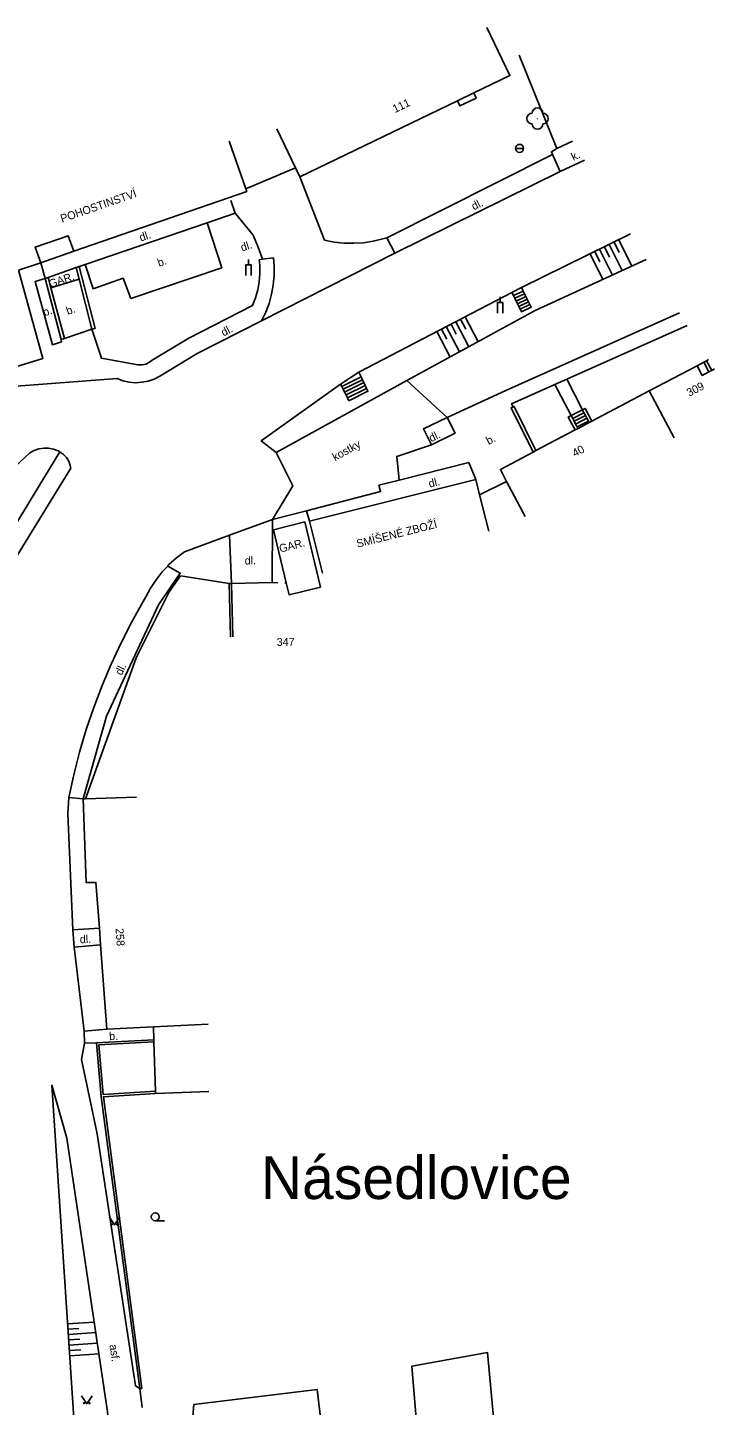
# Model space of a CAD drawing. Extents: x -582162 to -561283, y -1187583 to -1183539.
# Drawn here: x -574968.4 to -574904, y -1183847.8 to -1183718.7 of the extents above; entities that cross this region are included whole.
import ezdxf

# ---------------------------------------------------------------- set-up
doc = ezdxf.new("R2010")
doc.units = 0
for name, color, linetype in [('Vrstva 1', 7, 'Continuous'), ('Vrstva 10', 7, 'Continuous'), ('Vrstva 11', 7, 'Continuous'), ('Vrstva 12', 7, 'Continuous'), ('Vrstva 14', 7, 'Continuous'), ('Vrstva 17', 7, 'Continuous'), ('Vrstva 3', 7, 'Continuous'), ('Vrstva 4', 7, 'Continuous'), ('Vrstva 5', 7, 'Continuous'), ('Vrstva 6', 7, 'Continuous'), ('Vrstva 9', 7, 'Continuous')]:
    doc.layers.add(name, color=color, linetype=linetype)

# ---------------------------------------------------------------- blocks, each defined once
blk = doc.blocks.new('3.130')
at = {"layer": 'Vrstva 1'}
blk.add_circle((0, 0), 0.001, dxfattribs=at)
for centre, start, end in [((-1, 0), 90, 270), ((0, 1), 0, 180), ((1, 0), 270, 90), ((0, -1), 180, 360)]:
    blk.add_arc(centre, 1, start, end, dxfattribs=at)
blk = doc.blocks.new('3.040')
at = {"layer": 'Vrstva 1'}
blk.add_line((0, -0.75), (1.75, -0.75), dxfattribs=at)
blk.add_circle((0, 0), 0.75, dxfattribs=at)
blk = doc.blocks.new('3.140')
at = {"layer": 'Vrstva 1'}
blk.add_lwpolyline([(-1, 1.5), (0, 0), (1, 1.5)], dxfattribs=at)
for centre in [(-0.5, 0.1), (0.5, 0.1)]:
    blk.add_circle(centre, 0.1, dxfattribs=at)
blk = doc.blocks.new('4.120')
at = {"layer": 'Vrstva 1'}
blk.add_line((0, 2), (0, 3), dxfattribs=at)
blk.add_lwpolyline([(-0.5, 0), (-0.5, 2), (0.5, 2), (0.5, 0)], dxfattribs=at)
blk = doc.blocks.new('8.110')
at = {"layer": 'Vrstva 1'}
blk.add_line((-0.75, 0), (0.75, 0), dxfattribs=at)
blk.add_circle((0, 0), 0.75, dxfattribs=at)

msp = doc.modelspace()

# ---------------------------------------------------------------- linework, layer by layer
at = {"layer": 'Vrstva 10'}
for points in [[(-574918.8, -1183730.05), (-574922.35, -1183721.31)], [(-574919.2, -1183730.62), (-574919.32, -1183730.35), (-574918.8, -1183730.05)], [(-574918.8, -1183730.05), (-574917.33, -1183729.37)], [(-574934.73, -1183738.4), (-574919.2, -1183730.62)], [(-574919.2, -1183730.62), (-574918.49, -1183732.21)], [(-574918.49, -1183732.21), (-574916.22, -1183731.14)], [(-574942.91, -1183732.69), (-574940.59, -1183738.63), (-574939.69, -1183738.81), (-574938.77, -1183738.91), (-574937.85, -1183738.93), (-574936.92, -1183738.87), (-574936.01, -1183738.74), (-574935.12, -1183738.52), (-574934.73, -1183738.4)], [(-574934, -1183739.85), (-574918.49, -1183732.21)], [(-574949.38, -1183734.93), (-574948.96, -1183736.11)], [(-574951.6, -1183737), (-574948.96, -1183736.11)], [(-574948.96, -1183736.11), (-574947.29, -1183738.15), (-574946.82, -1183739.28), (-574946.41, -1183740.43)], [(-574963.02, -1183740.91), (-574951.6, -1183737)], [(-574934.73, -1183738.4), (-574934, -1183739.85)], [(-574911.91, -1183738.05), (-574922.12, -1183743.08)], [(-574946.41, -1183740.43), (-574946.71, -1183740.47), (-574946.66, -1183740.97), (-574946.64, -1183741.75), (-574946.7, -1183742.53), (-574946.84, -1183743.3), (-574947.06, -1183744.05), (-574947.35, -1183744.77), (-574953.31, -1183747.82), (-574956.73, -1183749.88), (-574956.99, -1183750.08), (-574957.33, -1183750.24), (-574957.7, -1183750.32), (-574958.08, -1183750.33), (-574961.5, -1183749.7), (-574962.39, -1183746.99)], [(-574946.48, -1183746.19), (-574934, -1183739.85)], [(-574946.48, -1183746.19), (-574946.1, -1183745.39), (-574945.78, -1183744.56), (-574945.55, -1183743.71), (-574945.39, -1183742.84), (-574945.31, -1183741.96), (-574945.31, -1183741.07), (-574945.38, -1183740.28), (-574946.41, -1183740.43)], [(-574932.86, -1183751.8), (-574920.83, -1183745.22), (-574910.42, -1183740.45)], [(-574969.26, -1183741.46), (-574966.98, -1183749.72), (-574970.34, -1183750.75)], [(-574966.79, -1183742.22), (-574967.19, -1183740.75)], [(-574963.87, -1183741.21), (-574966.5, -1183742.12)], [(-574963.58, -1183741.11), (-574963.87, -1183741.21)], [(-574963.02, -1183740.91), (-574963.58, -1183741.11)], [(-574962.29, -1183743.19), (-574963.02, -1183740.91)], [(-574965.26, -1183747.93), (-574965.23, -1183748.17), (-574966.1, -1183748.44), (-574967.72, -1183742.52), (-574966.79, -1183742.22)], [(-574966.5, -1183742.12), (-574966.79, -1183742.22)], [(-574923.01, -1183743.54), (-574937.36, -1183751)], [(-574929.1, -1183755.24), (-574923.6, -1183752.73), (-574907.31, -1183745.43)], [(-574946.48, -1183746.19), (-574952.52, -1183749.26), (-574956.03, -1183751.39), (-574956.56, -1183751.65), (-574957.12, -1183751.84), (-574957.71, -1183751.95), (-574958.3, -1183751.99), (-574958.9, -1183751.94), (-574959.48, -1183751.81), (-574960.04, -1183751.61), (-574969.88, -1183752.34)], [(-574906.58, -1183746.62), (-574917.88, -1183751.67)], [(-574962.39, -1183746.99), (-574964.97, -1183747.86)], [(-574945.12, -1183758.54), (-574946.51, -1183757.43), (-574939.08, -1183752.13)], [(-574945.12, -1183758.54), (-574932.86, -1183751.8)], [(-574929.1, -1183755.24), (-574932.86, -1183751.8)], [(-574917.88, -1183751.67), (-574918.98, -1183752.15)], [(-574917.88, -1183751.67), (-574916.41, -1183754.54)], [(-574918.98, -1183752.15), (-574923.04, -1183753.97), (-574922.9, -1183754.25)], [(-574917.47, -1183755.07), (-574918.98, -1183752.15)], [(-574930.54, -1183757.82), (-574931.32, -1183756.32), (-574929.1, -1183755.24)], [(-574930.54, -1183757.82), (-574928.34, -1183756.73), (-574929.1, -1183755.24)], [(-574965.4, -1183758.48), (-574965.57, -1183758.39), (-574966, -1183758.22), (-574966.45, -1183758.13), (-574966.91, -1183758.12), (-574967.36, -1183758.19), (-574967.8, -1183758.34), (-574968.2, -1183758.56), (-574984.34, -1183773.6)], [(-574973.93, -1183786.74), (-574974.04, -1183777.79), (-574970.76, -1183770.38), (-574964.37, -1183760), (-574964.42, -1183759.74), (-574964.57, -1183759.36), (-574964.79, -1183759.01), (-574965.07, -1183758.72), (-574965.4, -1183758.48)], [(-574965.4, -1183758.48), (-574972.13, -1183769.48), (-574973.68, -1183772.66)], [(-574945.12, -1183758.54), (-574943.56, -1183761.66), (-574945.47, -1183764.82)], [(-574933.58, -1183761.12), (-574933.81, -1183758.9), (-574930.54, -1183757.82)], [(-574933.58, -1183761.12), (-574927.06, -1183759.46), (-574926.4, -1183761.05)], [(-574942.29, -1183763.99), (-574935.33, -1183762.19), (-574935.49, -1183761.6), (-574933.58, -1183761.12)], [(-574945.47, -1183764.82), (-574949.5, -1183766.29)], [(-574945.47, -1183764.82), (-574945.49, -1183770.7)], [(-574942.29, -1183763.99), (-574945.47, -1183764.82)], [(-574941.99, -1183764.98), (-574942.29, -1183763.99)], [(-574949.5, -1183766.29), (-574953.71, -1183767.83), (-574954.47, -1183768.41), (-574955.17, -1183769.04), (-574955.29, -1183769.17)], [(-574949.5, -1183766.29), (-574949.32, -1183770.8)], [(-574955.29, -1183769.17), (-574955.81, -1183769.72), (-574956.38, -1183770.46), (-574956.9, -1183771.25), (-574957.34, -1183772.07), (-574957.59, -1183772.5), (-574958.66, -1183774.41), (-574959.66, -1183776.37), (-574960.59, -1183778.36), (-574961.44, -1183780.38), (-574962.22, -1183782.43), (-574962.92, -1183784.5), (-574963.55, -1183786.61), (-574964.1, -1183788.73), (-574964.57, -1183790.87)], [(-574955.29, -1183769.17), (-574954.11, -1183769.84), (-574956.14, -1183772.82), (-574961.03, -1183783.25), (-574963.2, -1183790.99)], [(-574964.57, -1183790.87), (-574964.64, -1183792.4), (-574964.19, -1183803.27)], [(-574963.2, -1183790.99), (-574964.57, -1183790.87)], [(-574964.19, -1183803.27), (-574961.69, -1183803.12)], [(-574964.19, -1183803.27), (-574964.06, -1183804.88)], [(-574964.06, -1183804.88), (-574961.58, -1183804.66)], [(-574964.06, -1183804.88), (-574963.12, -1183812.75)], [(-574963.12, -1183812.75), (-574961, -1183812.57)], [(-574963.12, -1183812.75), (-574963.08, -1183813.89)], [(-574963.08, -1183813.89), (-574963.38, -1183815.41), (-574961.9, -1183822.39), (-574958.31, -1183845.99), (-574957.91, -1183846.26)], [(-574963.08, -1183813.89), (-574961.95, -1183813.84)], [(-574962.62, -1183871.23), (-574966.14, -1183817.83), (-574964.73, -1183822.79), (-574960.94, -1183848.43), (-574960.22, -1183856.5)]]:
    msp.add_lwpolyline(points, dxfattribs=at)
at = {"layer": 'Vrstva 12'}
for points in [[(-574913.89, -1183739.03), (-574912.68, -1183741.49)], [(-574913.44, -1183738.81), (-574912.96, -1183739.8)], [(-574912.99, -1183738.59), (-574911.77, -1183741.07)], [(-574915.69, -1183739.92), (-574914.5, -1183742.32)], [(-574915.24, -1183739.69), (-574914.76, -1183740.66)], [(-574914.79, -1183739.47), (-574913.59, -1183741.91)], [(-574914.34, -1183739.25), (-574913.86, -1183740.23)], [(-574929.61, -1183746.97), (-574929.12, -1183747.92)], [(-574929.17, -1183746.74), (-574927.94, -1183749.11)], [(-574928.72, -1183746.51), (-574928.23, -1183747.45)], [(-574928.28, -1183746.28), (-574927.06, -1183748.63)], [(-574927.84, -1183746.05), (-574927.35, -1183746.98)], [(-574927.39, -1183745.82), (-574926.18, -1183748.15)], [(-574930.06, -1183747.2), (-574928.81, -1183749.59)], [(-574964.67, -1183840.18), (-574962.19, -1183840.02)], [(-574964.64, -1183840.68), (-574963.63, -1183840.62)], [(-574964.6, -1183841.18), (-574962.04, -1183841.01)], [(-574964.57, -1183841.68), (-574963.53, -1183841.61)], [(-574964.54, -1183842.18), (-574961.89, -1183842)], [(-574964.5, -1183842.68), (-574963.43, -1183842.61)], [(-574964.47, -1183843.18), (-574961.75, -1183843)]]:
    msp.add_lwpolyline(points, dxfattribs=at)
at = {"layer": 'Vrstva 4'}
for points in [[(-574926.59, -1183724.84), (-574923.2, -1183723.21), (-574925.37, -1183718.71)], [(-574928.13, -1183725.58), (-574926.59, -1183724.84)], [(-574942.91, -1183732.69), (-574928.13, -1183725.58)], [(-574945.07, -1183728.19), (-574943.32, -1183731.84)], [(-574949.51, -1183729.35), (-574947.96, -1183733.83)], [(-574943.32, -1183731.84), (-574942.91, -1183732.69)], [(-574947.96, -1183733.83), (-574947.88, -1183734.07), (-574964.1, -1183739.68)], [(-574964.1, -1183739.68), (-574964.61, -1183738.22), (-574967.7, -1183739.29), (-574967.19, -1183740.75)], [(-574964.1, -1183739.68), (-574967.19, -1183740.75)], [(-574967.19, -1183740.75), (-574969.26, -1183741.46)], [(-574910.14, -1183752.75), (-574905.66, -1183750.4)], [(-574905.66, -1183750.4), (-574905.18, -1183751.31), (-574904.55, -1183750.98)], [(-574904.55, -1183750.98), (-574904.28, -1183750.84)], [(-574904.28, -1183750.84), (-574904.03, -1183750.7)], [(-574915.51, -1183755.59), (-574910.14, -1183752.75)], [(-574907.8, -1183757.17), (-574910.14, -1183752.75)], [(-574916.81, -1183756.28), (-574915.78, -1183755.73)], [(-574915.78, -1183755.73), (-574915.51, -1183755.59)], [(-574920.76, -1183758.36), (-574917.08, -1183756.42)], [(-574917.08, -1183756.42), (-574916.81, -1183756.28)], [(-574923.51, -1183761.24), (-574924.1, -1183760.12), (-574921.02, -1183758.5)], [(-574921.02, -1183758.5), (-574920.76, -1183758.36)], [(-574941.99, -1183764.98), (-574926.4, -1183761.05)], [(-574926.4, -1183761.05), (-574926.04, -1183762.49)], [(-574921.77, -1183764.54), (-574923.51, -1183761.24)], [(-574926.04, -1183762.49), (-574925.18, -1183765.9)], [(-574942.44, -1183765.04), (-574945.38, -1183765.79), (-574944.18, -1183770.75)], [(-574944.18, -1183770.75), (-574943.91, -1183771.86), (-574940.96, -1183771.15), (-574942.44, -1183765.04)], [(-574940.77, -1183769.83), (-574941.99, -1183764.98)], [(-574963.2, -1183790.99), (-574962.99, -1183790.98), (-574958.21, -1183790.83)], [(-574961.69, -1183803.12), (-574962.01, -1183798.82), (-574962.94, -1183798.83), (-574963.2, -1183790.99)], [(-574961.58, -1183804.66), (-574961.69, -1183803.12)], [(-574961, -1183812.57), (-574961.58, -1183804.66)], [(-574956.63, -1183812.35), (-574961, -1183812.57)], [(-574951.5, -1183812.1), (-574956.63, -1183812.35)], [(-574956.63, -1183812.35), (-574956.59, -1183813.56)], [(-574956.59, -1183813.56), (-574956.58, -1183813.76)], [(-574956.58, -1183813.76), (-574956.43, -1183818.39)], [(-574956.43, -1183818.39), (-574956.42, -1183818.59)], [(-574956.42, -1183818.59), (-574951.42, -1183818.42)]]:
    msp.add_lwpolyline(points, dxfattribs=at)
at = {"layer": 'Vrstva 5'}
msp.add_lwpolyline([(-574953.37, -1183854.01), (-574952.83, -1183847.74), (-574941.28, -1183846.35), (-574940.53, -1183852.61), (-574946.79, -1183853.36), (-574947.56, -1183862.26), (-574938.66, -1183863.03), (-574938.82, -1183864.91), (-574930.62, -1183865.61), (-574932.39, -1183844.15), (-574925.3, -1183842.88), (-574923.17, -1183865.83), (-574921.49, -1183866.05), (-574921.56, -1183868.59)], dxfattribs=at)
at = {"layer": 'Vrstva 9'}
for points in [[(-574928.13, -1183725.58), (-574927.9, -1183726.06), (-574926.36, -1183725.32), (-574926.59, -1183724.84)], [(-574947.96, -1183733.83), (-574943.32, -1183731.84)], [(-574951.6, -1183737), (-574950.22, -1183741.22), (-574958.74, -1183744.1), (-574959.46, -1183742.21), (-574962.29, -1183743.19)], [(-574963.59, -1183742.3), (-574963.87, -1183741.21)], [(-574962.39, -1183746.99), (-574962.1, -1183746.91), (-574963.58, -1183741.11)], [(-574966.79, -1183742.22), (-574965.26, -1183747.93)], [(-574966.5, -1183742.12), (-574966.24, -1183743.1)], [(-574966.24, -1183743.1), (-574963.59, -1183742.3)], [(-574964.97, -1183747.86), (-574966.24, -1183743.1)], [(-574963.59, -1183742.3), (-574962.39, -1183746.99)], [(-574922.12, -1183743.08), (-574923.01, -1183743.54)], [(-574922.12, -1183743.08), (-574921.96, -1183743.4)], [(-574922.87, -1183743.83), (-574923.01, -1183743.54)], [(-574921.96, -1183743.4), (-574922.87, -1183743.83)], [(-574922.74, -1183744.08), (-574922.87, -1183743.83)], [(-574921.84, -1183743.65), (-574922.74, -1183744.08)], [(-574922.61, -1183744.34), (-574922.74, -1183744.08)], [(-574921.71, -1183743.91), (-574922.61, -1183744.34)], [(-574922.49, -1183744.59), (-574922.61, -1183744.34)], [(-574921.59, -1183744.16), (-574922.49, -1183744.59)], [(-574921.96, -1183743.4), (-574921.84, -1183743.65)], [(-574921.84, -1183743.65), (-574921.71, -1183743.91)], [(-574921.71, -1183743.91), (-574921.59, -1183744.16)], [(-574921.59, -1183744.16), (-574921.46, -1183744.41)], [(-574922.37, -1183744.84), (-574922.49, -1183744.59)], [(-574921.46, -1183744.41), (-574922.37, -1183744.84)], [(-574922.24, -1183745.09), (-574922.37, -1183744.84)], [(-574921.34, -1183744.66), (-574922.24, -1183745.09)], [(-574921.34, -1183744.66), (-574921.21, -1183744.91), (-574922.12, -1183745.34), (-574922.24, -1183745.09)], [(-574921.46, -1183744.41), (-574921.34, -1183744.66)], [(-574965.26, -1183747.93), (-574964.97, -1183747.86)], [(-574905.66, -1183750.4), (-574905.02, -1183750.07)], [(-574905.02, -1183750.07), (-574904.76, -1183749.93)], [(-574904.55, -1183750.98), (-574905.02, -1183750.07)], [(-574904.76, -1183749.93), (-574904.57, -1183749.83)], [(-574904.28, -1183750.84), (-574904.76, -1183749.93)], [(-574937.36, -1183751), (-574939.08, -1183752.13)], [(-574939.08, -1183752.13), (-574938.97, -1183752.34)], [(-574938.97, -1183752.34), (-574937.15, -1183751.44)], [(-574938.84, -1183752.6), (-574937.03, -1183751.71)], [(-574938.71, -1183752.87), (-574936.9, -1183751.98)], [(-574937.15, -1183751.44), (-574937.36, -1183751)], [(-574937.03, -1183751.71), (-574937.15, -1183751.44)], [(-574936.9, -1183751.98), (-574937.03, -1183751.71)], [(-574936.77, -1183752.25), (-574936.9, -1183751.98)], [(-574938.97, -1183752.34), (-574938.84, -1183752.6)], [(-574938.84, -1183752.6), (-574938.71, -1183752.87)], [(-574938.71, -1183752.87), (-574938.57, -1183753.14)], [(-574938.57, -1183753.14), (-574936.77, -1183752.25)], [(-574938.57, -1183753.14), (-574938.44, -1183753.41)], [(-574938.44, -1183753.41), (-574938.3, -1183753.68), (-574936.51, -1183752.79), (-574936.64, -1183752.52)], [(-574938.44, -1183753.41), (-574936.64, -1183752.52)], [(-574936.64, -1183752.52), (-574936.77, -1183752.25)], [(-574922.9, -1183754.25), (-574923.09, -1183754.34), (-574921.02, -1183758.5)], [(-574920.76, -1183758.36), (-574922.82, -1183754.21), (-574922.9, -1183754.25)], [(-574917.47, -1183755.07), (-574916.41, -1183754.54)], [(-574915.51, -1183755.59), (-574916.15, -1183754.4), (-574916.41, -1183754.54)], [(-574916.27, -1183754.8), (-574916.41, -1183754.54)], [(-574917.08, -1183756.42), (-574917.73, -1183755.22), (-574917.47, -1183755.07)], [(-574917.32, -1183755.34), (-574917.47, -1183755.07)], [(-574917.32, -1183755.34), (-574916.27, -1183754.8)], [(-574917.18, -1183755.6), (-574917.32, -1183755.34)], [(-574917.18, -1183755.6), (-574916.13, -1183755.07)], [(-574917.04, -1183755.87), (-574917.18, -1183755.6)], [(-574917.04, -1183755.87), (-574915.99, -1183755.33)], [(-574916.9, -1183756.13), (-574917.04, -1183755.87)], [(-574916.9, -1183756.13), (-574915.85, -1183755.6)], [(-574916.13, -1183755.07), (-574916.27, -1183754.8)], [(-574915.99, -1183755.33), (-574916.13, -1183755.07)], [(-574915.85, -1183755.6), (-574915.99, -1183755.33)], [(-574915.78, -1183755.73), (-574915.85, -1183755.6)], [(-574916.81, -1183756.28), (-574916.9, -1183756.13)], [(-574923.51, -1183761.24), (-574926.04, -1183762.49)], [(-574962.99, -1183790.98), (-574958.24, -1183777.77), (-574955.16, -1183771.59), (-574954.08, -1183770.1), (-574949.52, -1183770.8)], [(-574949.39, -1183775.8), (-574949.52, -1183770.8)], [(-574949.52, -1183770.8), (-574949.32, -1183770.8)], [(-574945.49, -1183770.7), (-574949.32, -1183770.8)], [(-574949.19, -1183775.8), (-574949.32, -1183770.8)], [(-574945.49, -1183770.7), (-574944.97, -1183770.75)], [(-574944.31, -1183770.75), (-574944.18, -1183770.75)], [(-574961.95, -1183813.84), (-574956.59, -1183813.56)], [(-574961.51, -1183818.92), (-574961.95, -1183813.84)], [(-574956.58, -1183813.76), (-574961.73, -1183814.03), (-574961.33, -1183818.71), (-574956.43, -1183818.39)], [(-574957.91, -1183846.26), (-574961.51, -1183818.92)], [(-574957.91, -1183846.26), (-574957.71, -1183846.24), (-574961.31, -1183818.91), (-574956.42, -1183818.59)], [(-574957.91, -1183846.26), (-574957.69, -1183848.02)]]:
    msp.add_lwpolyline(points, dxfattribs=at)

# ---------------------------------------------------------------- block references
at = {"layer": 'Vrstva 11', "xscale": 0.5, "yscale": 0.5}
msp.add_blockref('3.130', (-574920.62, -1183727.24), dxfattribs=at)
at = {"layer": 'Vrstva 3', "xscale": 0.5, "yscale": 0.5}
for name, p in [('3.140', (-574960.28, -1183830.92)), ('3.040', (-574956.46, -1183830.16)), ('3.140', (-574962.88, -1183847.67))]:
    msp.add_blockref(name, p, dxfattribs=at)
at = {"layer": 'Vrstva 9', "xscale": 0.5, "yscale": 0.5}
for name, p in [('8.110', (-574922.3, -1183730.03)), ('4.120', (-574947.7, -1183741.95)), ('4.120', (-574924.13, -1183745.46))]:
    msp.add_blockref(name, p, dxfattribs=at)

# ---------------------------------------------------------------- texts
at = {"layer": 'Vrstva 14'}
for s, rotation, p in [('k.', 26.214, (-574917.24, -1183731.21)), ('POHOSTINSTVÍ', 19.065, (-574965.19, -1183737)), ('dl.', 26.214, (-574926.58, -1183735.85)), ('dl.', 18.879, (-574957.8, -1183738.77)), ('dl.', 18.359, (-574948.31, -1183739.7)), ('b.', 18.879, (-574956.1, -1183741.14)), ('GAR.', 18.879, (-574966.28, -1183743.11)), ('b.', 18.879, (-574966.84, -1183745.78)), ('b.', 18.655, (-574964.66, -1183745.65)), ('dl.', 26.894, (-574950.05, -1183747.67)), ('dl.', 26.221, (-574930.58, -1183757.57)), ('b.', 27.845, (-574925.2, -1183757.83)), ('kostky', 28.818, (-574939.6, -1183759.35)), ('dl.', 14.139, (-574930.73, -1183761.83)), ('SMÍŠENÉ ZBOŽÍ', 14.139, (-574937.48, -1183767.46)), ('GAR.', 14.361, (-574944.73, -1183767.92)), ('dl.', 1.54, (-574948.06, -1183769.04)), ('dl.', 64.898, (-574959.59, -1183779.47)), ('dl.', 2.868, (-574963.51, -1183804.53)), ('b.', 2.868, (-574960.76, -1183813.61)), ('asf.', 278.393, (-574960.75, -1183842.17))]:
    msp.add_text(s, height=0.75, rotation=rotation, dxfattribs=at).set_placement(p)
at = {"layer": 'Vrstva 17'}
msp.add_text('Násedlovice', height=4, dxfattribs=at).set_placement((-574946.55, -1183828.49))
at = {"layer": 'Vrstva 6'}
for s, rotation, p in [('111', 25.694, (-574933.98, -1183726.73)), ('309', 27.65, (-574906.39, -1183753.32)), ('40', 27.845, (-574917.12, -1183758.98)), ('258', 274.192, (-574960.18, -1183803.14))]:
    msp.add_text(s, height=0.75, rotation=rotation, dxfattribs=at).set_placement(p)
msp.add_text('347', height=0.75, dxfattribs=at).set_placement((-574945.07, -1183776.66))

doc.saveas('drawing.dxf')
